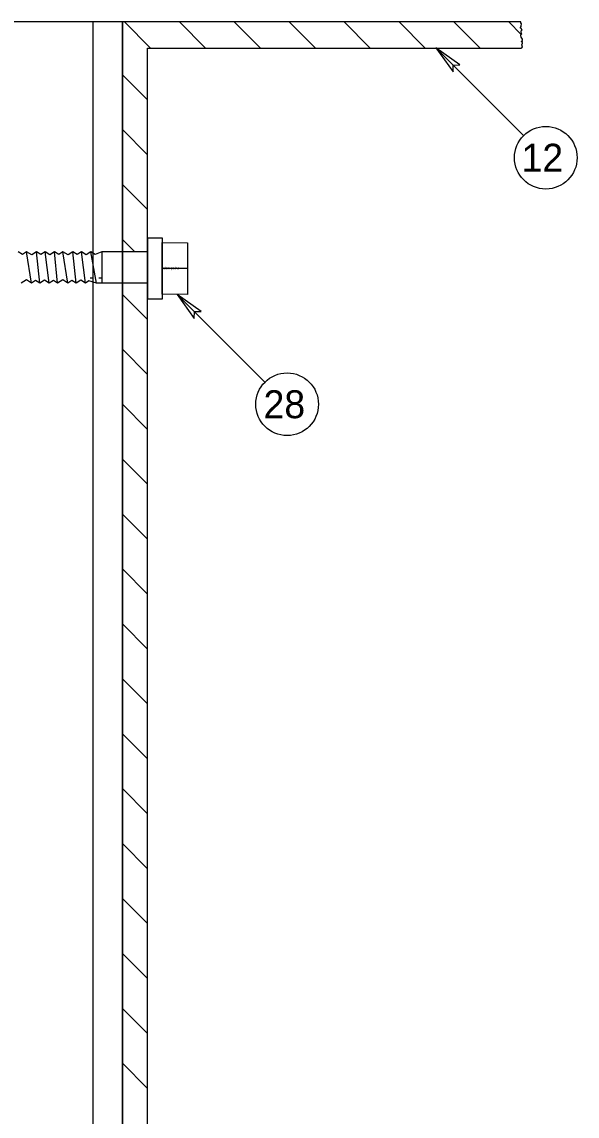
# Model space of a CAD drawing. Extents: x 99968 to 128667, y 90163 to 102182.
# Drawn here: x 111591.3 to 111829.6, y 94172.4 to 94642 of the extents above; entities that cross this region are included whole.
import ezdxf

# ---------------------------------------------------------------- set-up
doc = ezdxf.new("R2010")
doc.units = 0
doc.layers.add('RD Standard Plans Active', color=7, linetype='Continuous')

msp = doc.modelspace()

# ---------------------------------------------------------------- linework, layer by layer
at = {"layer": 'RD Standard Plans Active'}
for p, q in [((111621.8, 94642), (111621.8, 93918.47)), ((111634.41, 94642), (111634.41, 93918.47)), ((111646.55, 94630.76), (111635.31, 94642)), ((111670.12, 94630.76), (111658.88, 94642)), ((111693.69, 94630.76), (111682.45, 94642)), ((111717.26, 94630.76), (111706.02, 94642)), ((111740.83, 94630.76), (111729.59, 94642)), ((111764.4, 94630.76), (111753.16, 94642)), ((111787.97, 94630.76), (111776.73, 94642)), ((111805.65, 94636.65), (111800.3, 94642)), ((111769.04, 94630.83), (111806.67, 94593.21)), ((111645.19, 94608.55), (111634.41, 94619.33)), ((111645.19, 94584.98), (111634.41, 94595.76)), ((111645.19, 94561.41), (111634.41, 94572.19)), ((111639.7, 94543.33), (111634.41, 94548.62)), ((111591.52, 94542.17), (111589.68, 94543.32)), ((111593.3, 94543.32), (111591.52, 94542.17)), ((111595.34, 94529.93), (111593.3, 94543.32)), ((111595.49, 94541.96), (111593.3, 94543.32)), ((111597.61, 94543.32), (111595.49, 94541.96)), ((111598.96, 94529.93), (111597.61, 94543.32)), ((111599.45, 94542.17), (111597.61, 94543.32)), ((111601.23, 94543.32), (111599.45, 94542.17)), ((111603, 94529.93), (111601.23, 94543.32)), ((111603.29, 94542.04), (111601.23, 94543.32)), ((111605.28, 94543.32), (111603.29, 94542.04)), ((111606.62, 94529.93), (111605.28, 94543.32)), ((111607.12, 94542.17), (111605.28, 94543.32)), ((111608.9, 94543.32), (111607.12, 94542.17)), ((111610.94, 94529.93), (111608.9, 94543.32)), ((111611.09, 94541.96), (111608.9, 94543.32)), ((111613.21, 94543.32), (111611.09, 94541.96)), ((111614.56, 94529.93), (111613.21, 94543.32)), ((111615.05, 94542.17), (111613.21, 94543.32)), ((111616.83, 94543.32), (111615.05, 94542.17)), ((111618.6, 94529.93), (111616.83, 94543.32)), ((111618.89, 94542.04), (111616.83, 94543.32)), ((111620.88, 94543.32), (111618.89, 94542.04)), ((111623.32, 94529.93), (111620.88, 94543.32)), ((111622.72, 94542.17), (111620.88, 94543.32)), ((111625.64, 94543.33), (111622.72, 94542.17)), ((111645.19, 94543.33), (111625.64, 94543.33)), ((111625.64, 94543.33), (111625.64, 94529.88)), ((111620.63, 94532.11), (111621.64, 94532.11)), ((111624.25, 94532.11), (111625.26, 94532.11)), ((111662.33, 94536.2), (111651.46, 94536.2)), ((111593.22, 94531.29), (111591.02, 94529.93)), ((111595.34, 94529.93), (111593.22, 94531.29)), ((111597.18, 94531.07), (111595.34, 94529.93)), ((111598.96, 94529.93), (111597.18, 94531.07)), ((111601.01, 94531.21), (111598.96, 94529.93)), ((111603, 94529.93), (111601.01, 94531.21)), ((111604.84, 94531.07), (111603, 94529.93)), ((111606.62, 94529.93), (111604.84, 94531.07)), ((111608.82, 94531.29), (111606.62, 94529.93)), ((111610.94, 94529.93), (111608.82, 94531.29)), ((111612.78, 94531.07), (111610.94, 94529.93)), ((111614.56, 94529.93), (111612.78, 94531.07)), ((111616.61, 94531.21), (111614.56, 94529.93)), ((111618.6, 94529.93), (111616.61, 94531.21)), ((111620.07, 94530.84), (111618.6, 94529.93)), ((111623.32, 94529.93), (111620.07, 94530.84)), ((111645.19, 94529.93), (111623.32, 94529.93)), ((111645.19, 94514.27), (111634.41, 94525.05)), ((111658, 94525.04), (111695.63, 94487.42)), ((111645.19, 94490.7), (111634.41, 94501.48)), ((111645.19, 94467.13), (111634.41, 94477.91)), ((111645.19, 94443.56), (111634.41, 94454.34)), ((111645.19, 94419.99), (111634.41, 94430.77)), ((111645.19, 94396.42), (111634.41, 94407.2)), ((111645.19, 94372.85), (111634.41, 94383.63)), ((111645.19, 94349.28), (111634.41, 94360.06)), ((111645.19, 94325.71), (111634.41, 94336.49)), ((111645.19, 94302.14), (111634.41, 94312.92)), ((111645.19, 94278.57), (111634.41, 94289.35)), ((111645.19, 94255), (111634.41, 94265.78)), ((111645.19, 94231.43), (111634.41, 94242.21)), ((111645.19, 94207.86), (111634.41, 94218.64)), ((111645.19, 94184.29), (111634.41, 94195.07))]:
    msp.add_line(p, q, dxfattribs=at)
for points in [[(111634.41, 94642), (111510.68, 94642), (111510.68, 93918.47), (111634.41, 93918.47)], [(111779.32, 94623.54), (111769.04, 94630.83), (111776.34, 94620.56), (111776.44, 94623.43)], [(111645.35, 94549.35), (111651.45, 94549.35), (111651.45, 94523.05), (111645.35, 94523.05)], [(111668.28, 94517.75), (111658, 94525.04), (111665.3, 94514.77), (111665.4, 94517.64)]]:
    msp.add_lwpolyline(points, close=True, dxfattribs=at)
for points in [[(111805.51, 94642), (111634.41, 94642), (111634.41, 93918.47), (111805.51, 93918.47)], [(111805.51, 94630.76), (111806.19, 94631.17), (111806.19, 94631.17), (111805.94, 94632.08), (111806.19, 94632.85), (111806.19, 94633.1), (111805.65, 94633.55), (111806.17, 94634.03), (111806.17, 94634.57), (111805.67, 94635.41), (111805.42, 94636.09), (111805.42, 94636.45), (111805.92, 94636.88), (111805.62, 94637.45), (111805.62, 94637.7), (111805.62, 94638.13), (111805.96, 94638.54), (111805.96, 94638.54), (111805.58, 94639.15), (111805.24, 94639.46), (111805.53, 94639.99), (111805.53, 94640.3), (111805.53, 94640.3), (111805.78, 94641.16), (111805.51, 94641.53), (111805.51, 94642)], [(111805.54, 93928.32), (111645.19, 93928.3), (111645.19, 94630.76), (111805.51, 94630.76)], [(111651.46, 94532.1), (111651.46, 94547.28), (111662.33, 94547.2), (111662.33, 94525.04), (111651.48, 94525.12), (111651.48, 94532.1)]]:
    msp.add_lwpolyline(points, dxfattribs=at)
for centre in [(111816.18, 94583.7), (111705.14, 94477.91)]:
    msp.add_circle(centre, 13.44, dxfattribs=at)

# ---------------------------------------------------------------- texts
for s, height, p in [('12', 12, (111805.76, 94577.7)), ('alan paine', 1.1, (111651.89, 94535.77)), ('28', 12, (111695.02, 94471.91))]:
    msp.add_text(s, height=height, dxfattribs=at).set_placement(p)

doc.saveas('drawing.dxf')
